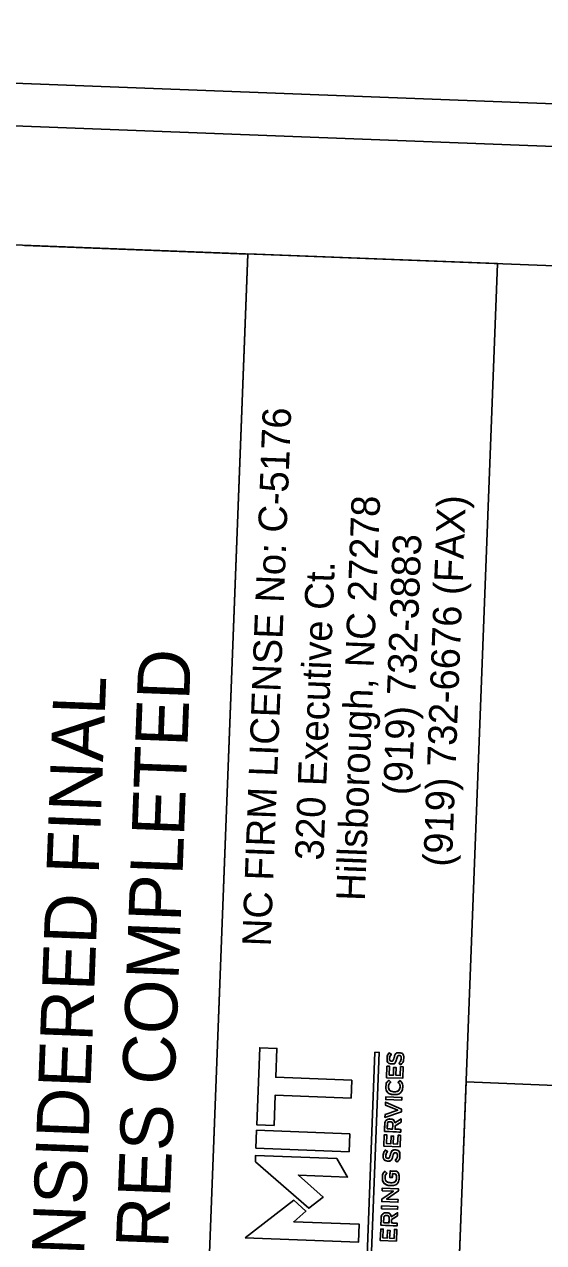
# Model space of a CAD drawing. Extents: x 2097096 to 2098260, y 686401 to 688363.
# Drawn here: x 2097322.3 to 2097376.9, y 688066.3 to 688194.3 of the extents above; entities that cross this region are included whole.
import ezdxf

# ---------------------------------------------------------------- set-up
doc = ezdxf.new("R2010")
doc.units = 0
for name, color, linetype in [('Sheet Block Title CELL', 7, 'Continuous'), ('Sheet Layout Plan Border', 7, 'Continuous'), ('Sheet Plot Border Inside CELL', 7, 'Continuous'), ('Sheet Plot Border Outside CELL', 7, 'Continuous'), ('Sheet Profile CELL', 7, 'Continuous'), ('Sheet Sticker Exception Certification CELL', 7, 'Continuous')]:
    doc.layers.add(name, color=color, linetype=linetype)

msp = doc.modelspace()

# ---------------------------------------------------------------- linework, layer by layer
at = {"layer": 'Sheet Block Title CELL'}
for p, q in [((2097360.85, 688086.12), (2097360.63, 688086.28)), ((2097361.66, 688086.29), (2097361.66, 688086.29)), ((2097360.86, 688085.41), (2097360.85, 688085.41)), ((2097360.87, 688085.12), (2097360.87, 688085.12)), ((2097361.64, 688085.2), (2097361.85, 688085.02)), ((2097361.67, 688086), (2097361.68, 688086)), ((2097360.78, 688083.2), (2097360.57, 688083.4)), ((2097361.76, 688083.36), (2097361.56, 688083.19)), ((2097361.14, 688082.19), (2097361.13, 688082.2)), ((2097361.13, 688081.89), (2097361.13, 688081.89)), ((2097360.72, 688079.33), (2097360.71, 688079.33)), ((2097360.72, 688079.04), (2097360.72, 688079.04)), ((2097360.46, 688075.91), (2097360.24, 688076.07)), ((2097361.27, 688076.08), (2097361.26, 688076.08)), ((2097360.47, 688075.2), (2097360.46, 688075.2)), ((2097360.48, 688074.91), (2097360.48, 688074.91)), ((2097361.25, 688074.99), (2097361.46, 688074.81)), ((2097361.28, 688075.79), (2097361.29, 688075.79)), ((2097360.39, 688073.64), (2097360.17, 688073.84)), ((2097360.76, 688072.34), (2097360.76, 688072.34)), ((2097360.77, 688072.64), (2097360.77, 688072.64)), ((2097360.34, 688069.48), (2097360.34, 688069.48)), ((2097360.34, 688069.19), (2097360.35, 688069.19))]:
    msp.add_line(p, q, dxfattribs=at)
msp.add_lwpolyline([(2097338.1, 687970.31), (2097345.76, 688170.22), (2097372, 688169.21), (2097364.33, 687969.3)], close=True, dxfattribs=at)
for points in [[(2097347.02, 688086.81), (2097348.83, 688086.74), (2097348.71, 688083.71), (2097356.69, 688083.4), (2097356.62, 688081.53), (2097348.64, 688081.83), (2097348.52, 688078.65), (2097346.71, 688078.72), (2097347.02, 688086.81)], [(2097346.71, 688078.72), (2097348.52, 688078.65), (2097348.64, 688081.83), (2097356.62, 688081.53), (2097356.69, 688083.4), (2097348.71, 688083.71), (2097348.83, 688086.74), (2097347.02, 688086.81), (2097346.71, 688078.72)], [(2097359.58, 688086.33), (2097357.83, 688040.83), (2097357.38, 688040.84), (2097359.13, 688086.35), (2097359.58, 688086.33)], [(2097359.13, 688086.35), (2097357.38, 688040.84), (2097357.83, 688040.83), (2097359.58, 688086.33), (2097359.13, 688086.35)], [(2097360.34, 688083.67), (2097360.39, 688084.88), (2097360.66, 688084.87), (2097360.62, 688083.95), (2097361.06, 688083.93), (2097361.09, 688084.75), (2097361.36, 688084.74), (2097361.33, 688083.92), (2097361.79, 688083.9), (2097361.82, 688084.84), (2097362.09, 688084.82), (2097362.04, 688083.61), (2097360.34, 688083.67)], [(2097362.04, 688083.61), (2097362.09, 688084.82), (2097361.82, 688084.84), (2097361.79, 688083.9), (2097361.33, 688083.92), (2097361.36, 688084.74), (2097361.09, 688084.75), (2097361.06, 688083.93), (2097360.62, 688083.95), (2097360.66, 688084.87), (2097360.39, 688084.88), (2097360.34, 688083.67), (2097362.04, 688083.61)], [(2097360.26, 688081.37), (2097360.27, 688081.66), (2097361.96, 688081.59), (2097361.95, 688081.31), (2097360.26, 688081.37)], [(2097361.95, 688081.31), (2097361.96, 688081.59), (2097360.27, 688081.66), (2097360.26, 688081.37), (2097361.95, 688081.31)], [(2097360.18, 688079.49), (2097360.2, 688079.81), (2097361.52, 688080.25), (2097360.23, 688080.79), (2097360.24, 688081.1), (2097361.93, 688080.36), (2097361.92, 688080.1), (2097360.18, 688079.49)], [(2097361.92, 688080.1), (2097361.93, 688080.36), (2097360.24, 688081.1), (2097360.23, 688080.79), (2097361.52, 688080.25), (2097360.2, 688079.81), (2097360.18, 688079.49), (2097361.92, 688080.1)], [(2097360.15, 688078.75), (2097360.13, 688078.02), (2097361.83, 688077.95), (2097361.84, 688078.24), (2097361.24, 688078.26), (2097361.26, 688078.62), (2097361.87, 688079), (2097361.88, 688079.34), (2097361.22, 688078.92)], [(2097361, 688078.69), (2097360.98, 688078.27), (2097360.41, 688078.3), (2097360.43, 688078.71)], [(2097346.62, 688076.27), (2097346.69, 688078.15), (2097356.48, 688077.77), (2097356.41, 688075.89), (2097346.62, 688076.27)], [(2097356.41, 688075.89), (2097356.48, 688077.77), (2097346.69, 688078.15), (2097346.62, 688076.27), (2097356.41, 688075.89)], [(2097360.07, 688076.46), (2097360.11, 688077.67), (2097360.38, 688077.66), (2097360.34, 688076.74), (2097360.79, 688076.72), (2097360.82, 688077.54), (2097361.08, 688077.53), (2097361.05, 688076.71), (2097361.51, 688076.69), (2097361.55, 688077.63), (2097361.81, 688077.62), (2097361.77, 688076.4), (2097360.07, 688076.46)], [(2097361.77, 688076.4), (2097361.81, 688077.62), (2097361.55, 688077.63), (2097361.51, 688076.69), (2097361.05, 688076.71), (2097361.08, 688077.53), (2097360.82, 688077.54), (2097360.79, 688076.72), (2097360.34, 688076.74), (2097360.38, 688077.66), (2097360.11, 688077.67), (2097360.07, 688076.46), (2097361.77, 688076.4)], [(2097346.56, 688074.84), (2097352.18, 688069.95), (2097353.69, 688071.13), (2097351.08, 688073.43), (2097356.25, 688073.23), (2097355.12, 688075.17), (2097346.59, 688075.5), (2097346.56, 688074.84)], [(2097346.56, 688074.84), (2097352.18, 688069.95), (2097353.69, 688071.13), (2097351.08, 688073.43), (2097356.25, 688073.23), (2097355.12, 688075.17), (2097346.59, 688075.5), (2097346.56, 688074.84)], [(2097361.43, 688073.85), (2097360.72, 688073.87), (2097360.69, 688073.18), (2097360.95, 688073.17), (2097360.97, 688073.59), (2097361.29, 688073.57)], [(2097359.84, 688070.66), (2097359.85, 688070.92), (2097361.06, 688071.75), (2097359.89, 688071.79), (2097359.9, 688072.08), (2097361.6, 688072.01), (2097361.59, 688071.77), (2097360.35, 688070.92), (2097361.55, 688070.87), (2097361.54, 688070.59), (2097359.84, 688070.66)], [(2097361.54, 688070.59), (2097361.55, 688070.87), (2097360.35, 688070.92), (2097361.59, 688071.77), (2097361.6, 688072.01), (2097359.9, 688072.08), (2097359.89, 688071.79), (2097361.06, 688071.75), (2097359.85, 688070.92), (2097359.84, 688070.66), (2097361.54, 688070.59)], [(2097345.48, 688066.86), (2097357.4, 688066.4), (2097357.47, 688068.28), (2097350.59, 688068.54), (2097351.87, 688069.66), (2097350.61, 688070.8), (2097345.48, 688066.86)], [(2097345.48, 688066.86), (2097357.4, 688066.4), (2097357.47, 688068.28), (2097350.59, 688068.54), (2097351.87, 688069.66), (2097350.61, 688070.8), (2097345.48, 688066.86)], [(2097359.82, 688069.91), (2097359.83, 688070.2), (2097361.53, 688070.13), (2097361.51, 688069.85), (2097359.82, 688069.91)], [(2097361.51, 688069.85), (2097361.53, 688070.13), (2097359.83, 688070.2), (2097359.82, 688069.91), (2097361.51, 688069.85)], [(2097359.78, 688068.89), (2097359.75, 688068.17), (2097361.45, 688068.1), (2097361.46, 688068.39), (2097360.87, 688068.41), (2097360.88, 688068.77), (2097361.49, 688069.15), (2097361.5, 688069.49), (2097360.84, 688069.07)], [(2097360.62, 688068.84), (2097360.6, 688068.42), (2097360.03, 688068.44), (2097360.05, 688068.86)], [(2097359.69, 688066.56), (2097359.73, 688067.77), (2097360, 688067.76), (2097359.97, 688066.84), (2097360.41, 688066.82), (2097360.44, 688067.64), (2097360.71, 688067.63), (2097360.67, 688066.81), (2097361.13, 688066.79), (2097361.17, 688067.73), (2097361.43, 688067.72), (2097361.39, 688066.5), (2097359.69, 688066.56)], [(2097361.39, 688066.5), (2097361.43, 688067.72), (2097361.17, 688067.73), (2097361.13, 688066.79), (2097360.67, 688066.81), (2097360.71, 688067.63), (2097360.44, 688067.64), (2097360.41, 688066.82), (2097359.97, 688066.84), (2097360, 688067.76), (2097359.73, 688067.77), (2097359.69, 688066.56), (2097361.39, 688066.5)]]:
    msp.add_lwpolyline(points, dxfattribs=at)
for points, degree in [([(2097361.85, 688085.02), (2097361.85, 688085.02), (2097361.64, 688085.2), (2097361.64, 688085.2), (2097361.79, 688085.35), (2097361.87, 688085.5), (2097361.88, 688085.7), (2097361.89, 688085.88), (2097361.81, 688086), (2097361.68, 688086), (2097361.68, 688086), (2097361.67, 688086), (2097361.67, 688086), (2097361.55, 688086.01), (2097361.49, 688085.94), (2097361.4, 688085.64), (2097361.3, 688085.3), (2097361.19, 688085.11), (2097360.87, 688085.12), (2097360.87, 688085.12), (2097360.87, 688085.12), (2097360.87, 688085.12), (2097360.58, 688085.13), (2097360.38, 688085.37), (2097360.4, 688085.7), (2097360.41, 688085.93), (2097360.49, 688086.12), (2097360.63, 688086.28), (2097360.63, 688086.28), (2097360.85, 688086.12), (2097360.85, 688086.12), (2097360.73, 688085.97), (2097360.67, 688085.83), (2097360.66, 688085.68), (2097360.65, 688085.51), (2097360.74, 688085.41), (2097360.85, 688085.41), (2097360.85, 688085.41), (2097360.86, 688085.41), (2097360.86, 688085.41), (2097360.99, 688085.4), (2097361.05, 688085.48), (2097361.14, 688085.79), (2097361.24, 688086.13), (2097361.37, 688086.3), (2097361.66, 688086.29), (2097361.66, 688086.29), (2097361.66, 688086.29), (2097361.66, 688086.29), (2097361.98, 688086.28), (2097362.16, 688086.03), (2097362.15, 688085.69), (2097362.14, 688085.44), (2097362.04, 688085.21), (2097361.85, 688085.02)], 3), ([(2097360.63, 688086.28), (2097360.49, 688086.12), (2097360.41, 688085.93), (2097360.4, 688085.7), (2097360.38, 688085.37), (2097360.58, 688085.13), (2097360.87, 688085.12)], 3), ([(2097361.66, 688086.29), (2097361.37, 688086.3), (2097361.24, 688086.13), (2097361.14, 688085.79), (2097361.05, 688085.48), (2097360.99, 688085.4), (2097360.86, 688085.41)], 3), ([(2097361.85, 688085.02), (2097362.04, 688085.21), (2097362.14, 688085.44), (2097362.15, 688085.69), (2097362.16, 688086.03), (2097361.98, 688086.28), (2097361.66, 688086.29)], 3), ([(2097360.85, 688085.41), (2097360.74, 688085.41), (2097360.65, 688085.51), (2097360.66, 688085.68), (2097360.67, 688085.83), (2097360.73, 688085.97), (2097360.85, 688086.12)], 3), ([(2097360.87, 688085.12), (2097361.19, 688085.11), (2097361.3, 688085.3), (2097361.4, 688085.64), (2097361.49, 688085.94), (2097361.55, 688086.01), (2097361.67, 688086)], 3), ([(2097361.68, 688086), (2097361.81, 688086), (2097361.89, 688085.88), (2097361.88, 688085.7), (2097361.87, 688085.5), (2097361.79, 688085.35), (2097361.64, 688085.2)], 3), ([(2097361.13, 688081.89), (2097361.13, 688081.89), (2097361.13, 688081.89), (2097361.13, 688081.89), (2097360.64, 688081.91), (2097360.26, 688082.28), (2097360.28, 688082.77), (2097360.29, 688083.07), (2097360.41, 688083.25), (2097360.57, 688083.4), (2097360.57, 688083.4), (2097360.78, 688083.2), (2097360.78, 688083.2), (2097360.65, 688083.08), (2097360.56, 688082.94), (2097360.55, 688082.76), (2097360.54, 688082.45), (2097360.8, 688082.21), (2097361.13, 688082.2), (2097361.13, 688082.2), (2097361.14, 688082.19), (2097361.14, 688082.19), (2097361.47, 688082.18), (2097361.75, 688082.4), (2097361.76, 688082.71), (2097361.77, 688082.91), (2097361.69, 688083.04), (2097361.56, 688083.19), (2097361.56, 688083.19), (2097361.76, 688083.36), (2097361.76, 688083.36), (2097361.94, 688083.19), (2097362.05, 688082.99), (2097362.04, 688082.69), (2097362.02, 688082.21), (2097361.62, 688081.88), (2097361.13, 688081.89)], 3), ([(2097360.57, 688083.4), (2097360.41, 688083.25), (2097360.29, 688083.07), (2097360.28, 688082.77), (2097360.26, 688082.28), (2097360.64, 688081.91), (2097361.13, 688081.89)], 3), ([(2097361.13, 688082.2), (2097360.8, 688082.21), (2097360.54, 688082.45), (2097360.55, 688082.76), (2097360.56, 688082.94), (2097360.65, 688083.08), (2097360.78, 688083.2)], 3), ([(2097361.13, 688081.89), (2097361.62, 688081.88), (2097362.02, 688082.21), (2097362.04, 688082.69), (2097362.05, 688082.99), (2097361.94, 688083.19), (2097361.76, 688083.36)], 3), ([(2097361.56, 688083.19), (2097361.69, 688083.04), (2097361.77, 688082.91), (2097361.76, 688082.71), (2097361.75, 688082.4), (2097361.47, 688082.18), (2097361.14, 688082.19)], 3), ([(2097360.13, 688078.02), (2097360.13, 688078.02), (2097360.15, 688078.75), (2097360.15, 688078.75), (2097360.16, 688078.95), (2097360.23, 688079.11), (2097360.34, 688079.21), (2097360.44, 688079.29), (2097360.57, 688079.34), (2097360.71, 688079.33), (2097360.71, 688079.33), (2097360.72, 688079.33), (2097360.72, 688079.33), (2097361, 688079.32), (2097361.16, 688079.15), (2097361.22, 688078.92), (2097361.22, 688078.92), (2097361.88, 688079.34), (2097361.88, 688079.34), (2097361.88, 688079.34), (2097361.87, 688079), (2097361.87, 688079), (2097361.87, 688079), (2097361.26, 688078.62), (2097361.26, 688078.62), (2097361.26, 688078.62), (2097361.24, 688078.26), (2097361.24, 688078.26), (2097361.24, 688078.26), (2097361.84, 688078.24), (2097361.84, 688078.24), (2097361.84, 688078.24), (2097361.83, 688077.95), (2097361.83, 688077.95), (2097361.83, 688077.95), (2097360.13, 688078.02), (2097360.13, 688078.02)], 3), ([(2097360.71, 688079.33), (2097360.57, 688079.34), (2097360.44, 688079.29), (2097360.34, 688079.21), (2097360.23, 688079.11), (2097360.16, 688078.95), (2097360.15, 688078.75)], 3), ([(2097361, 688078.69), (2097361, 688078.9), (2097360.9, 688079.03), (2097360.72, 688079.04), (2097360.72, 688079.04), (2097360.72, 688079.04), (2097360.72, 688079.04), (2097360.54, 688079.05), (2097360.43, 688078.92), (2097360.43, 688078.71), (2097360.43, 688078.71), (2097360.41, 688078.3), (2097360.41, 688078.3), (2097360.41, 688078.3), (2097360.98, 688078.27), (2097360.98, 688078.27), (2097360.98, 688078.27), (2097361, 688078.69), (2097361, 688078.69)], 3), ([(2097360.43, 688078.71), (2097360.43, 688078.92), (2097360.54, 688079.05), (2097360.72, 688079.04)], 2), ([(2097361.22, 688078.92), (2097361.16, 688079.15), (2097361, 688079.32), (2097360.72, 688079.33)], 2), ([(2097360.72, 688079.04), (2097360.9, 688079.03), (2097361, 688078.9), (2097361, 688078.69)], 2), ([(2097361.46, 688074.81), (2097361.46, 688074.81), (2097361.25, 688074.99), (2097361.25, 688074.99), (2097361.4, 688075.14), (2097361.48, 688075.29), (2097361.49, 688075.49), (2097361.5, 688075.67), (2097361.41, 688075.78), (2097361.29, 688075.79), (2097361.29, 688075.79), (2097361.28, 688075.79), (2097361.28, 688075.79), (2097361.16, 688075.79), (2097361.09, 688075.73), (2097361.01, 688075.43), (2097360.91, 688075.09), (2097360.79, 688074.9), (2097360.48, 688074.91), (2097360.48, 688074.91), (2097360.48, 688074.91), (2097360.48, 688074.91), (2097360.19, 688074.92), (2097359.99, 688075.16), (2097360, 688075.48), (2097360.01, 688075.72), (2097360.1, 688075.91), (2097360.24, 688076.07), (2097360.24, 688076.07), (2097360.46, 688075.91), (2097360.46, 688075.91), (2097360.34, 688075.76), (2097360.28, 688075.62), (2097360.27, 688075.47), (2097360.26, 688075.3), (2097360.35, 688075.2), (2097360.46, 688075.2), (2097360.46, 688075.2), (2097360.47, 688075.2), (2097360.47, 688075.2), (2097360.6, 688075.19), (2097360.66, 688075.26), (2097360.75, 688075.57), (2097360.85, 688075.92), (2097360.98, 688076.09), (2097361.26, 688076.08), (2097361.26, 688076.08), (2097361.27, 688076.08), (2097361.27, 688076.08), (2097361.59, 688076.06), (2097361.77, 688075.82), (2097361.75, 688075.48), (2097361.75, 688075.23), (2097361.65, 688074.99), (2097361.46, 688074.81)], 3), ([(2097360.24, 688076.07), (2097360.1, 688075.91), (2097360.01, 688075.72), (2097360, 688075.48), (2097359.99, 688075.16), (2097360.19, 688074.92), (2097360.48, 688074.91)], 3), ([(2097361.26, 688076.08), (2097360.98, 688076.09), (2097360.85, 688075.92), (2097360.75, 688075.57), (2097360.66, 688075.26), (2097360.6, 688075.19), (2097360.47, 688075.2)], 3), ([(2097361.46, 688074.81), (2097361.65, 688074.99), (2097361.75, 688075.23), (2097361.75, 688075.48), (2097361.77, 688075.82), (2097361.59, 688076.06), (2097361.27, 688076.08)], 3), ([(2097360.46, 688075.2), (2097360.35, 688075.2), (2097360.26, 688075.3), (2097360.27, 688075.47), (2097360.28, 688075.62), (2097360.34, 688075.76), (2097360.46, 688075.91)], 3), ([(2097360.48, 688074.91), (2097360.79, 688074.9), (2097360.91, 688075.09), (2097361.01, 688075.43), (2097361.09, 688075.73), (2097361.16, 688075.79), (2097361.28, 688075.79)], 3), ([(2097361.29, 688075.79), (2097361.41, 688075.78), (2097361.5, 688075.67), (2097361.49, 688075.49), (2097361.48, 688075.29), (2097361.4, 688075.14), (2097361.25, 688074.99)], 3), ([(2097360.76, 688072.34), (2097360.76, 688072.34), (2097360.76, 688072.34), (2097360.76, 688072.34), (2097360.28, 688072.36), (2097359.89, 688072.73), (2097359.91, 688073.22), (2097359.92, 688073.5), (2097360.01, 688073.67), (2097360.17, 688073.84), (2097360.17, 688073.84), (2097360.39, 688073.64), (2097360.39, 688073.64), (2097360.27, 688073.52), (2097360.19, 688073.4), (2097360.19, 688073.2), (2097360.18, 688072.9), (2097360.44, 688072.66), (2097360.77, 688072.64), (2097360.77, 688072.64), (2097360.77, 688072.64), (2097360.77, 688072.64), (2097361.12, 688072.63), (2097361.39, 688072.84), (2097361.4, 688073.17), (2097361.4, 688073.33), (2097361.36, 688073.47), (2097361.29, 688073.57), (2097361.29, 688073.57), (2097360.97, 688073.59), (2097360.97, 688073.59), (2097360.97, 688073.59), (2097360.95, 688073.17), (2097360.95, 688073.17), (2097360.95, 688073.17), (2097360.69, 688073.18), (2097360.69, 688073.18), (2097360.69, 688073.18), (2097360.72, 688073.87), (2097360.72, 688073.87), (2097360.72, 688073.87), (2097361.43, 688073.85), (2097361.43, 688073.85), (2097361.57, 688073.68), (2097361.68, 688073.44), (2097361.67, 688073.15), (2097361.65, 688072.65), (2097361.26, 688072.32), (2097360.76, 688072.34)], 3), ([(2097360.17, 688073.84), (2097360.01, 688073.67), (2097359.92, 688073.5), (2097359.91, 688073.22), (2097359.89, 688072.73), (2097360.28, 688072.36), (2097360.76, 688072.34)], 3), ([(2097360.77, 688072.64), (2097360.44, 688072.66), (2097360.18, 688072.9), (2097360.19, 688073.2), (2097360.19, 688073.4), (2097360.27, 688073.52), (2097360.39, 688073.64)], 3), ([(2097360.76, 688072.34), (2097361.26, 688072.32), (2097361.65, 688072.65), (2097361.67, 688073.15), (2097361.68, 688073.44), (2097361.57, 688073.68), (2097361.43, 688073.85)], 3), ([(2097361.29, 688073.57), (2097361.36, 688073.47), (2097361.4, 688073.33), (2097361.4, 688073.17), (2097361.39, 688072.84), (2097361.12, 688072.63), (2097360.77, 688072.64)], 3), ([(2097359.75, 688068.17), (2097359.75, 688068.17), (2097359.78, 688068.89), (2097359.78, 688068.89), (2097359.78, 688069.1), (2097359.85, 688069.26), (2097359.96, 688069.36), (2097360.06, 688069.44), (2097360.19, 688069.48), (2097360.34, 688069.48), (2097360.34, 688069.48), (2097360.34, 688069.48), (2097360.34, 688069.48), (2097360.62, 688069.47), (2097360.78, 688069.3), (2097360.84, 688069.07), (2097360.84, 688069.07), (2097361.5, 688069.49), (2097361.5, 688069.49), (2097361.5, 688069.49), (2097361.49, 688069.15), (2097361.49, 688069.15), (2097361.49, 688069.15), (2097360.88, 688068.77), (2097360.88, 688068.77), (2097360.88, 688068.77), (2097360.87, 688068.41), (2097360.87, 688068.41), (2097360.87, 688068.41), (2097361.46, 688068.39), (2097361.46, 688068.39), (2097361.46, 688068.39), (2097361.45, 688068.1), (2097361.45, 688068.1), (2097361.45, 688068.1), (2097359.75, 688068.17), (2097359.75, 688068.17)], 3), ([(2097360.34, 688069.48), (2097360.19, 688069.48), (2097360.06, 688069.44), (2097359.96, 688069.36), (2097359.85, 688069.26), (2097359.78, 688069.1), (2097359.78, 688068.89)], 3), ([(2097360.62, 688068.84), (2097360.63, 688069.04), (2097360.52, 688069.18), (2097360.35, 688069.19), (2097360.35, 688069.19), (2097360.34, 688069.19), (2097360.34, 688069.19), (2097360.16, 688069.19), (2097360.06, 688069.07), (2097360.05, 688068.86), (2097360.05, 688068.86), (2097360.03, 688068.44), (2097360.03, 688068.44), (2097360.03, 688068.44), (2097360.6, 688068.42), (2097360.6, 688068.42), (2097360.6, 688068.42), (2097360.62, 688068.84), (2097360.62, 688068.84)], 3), ([(2097360.05, 688068.86), (2097360.06, 688069.07), (2097360.16, 688069.19), (2097360.34, 688069.19)], 2), ([(2097360.84, 688069.07), (2097360.78, 688069.3), (2097360.62, 688069.47), (2097360.34, 688069.48)], 2), ([(2097360.35, 688069.19), (2097360.52, 688069.18), (2097360.63, 688069.04), (2097360.62, 688068.84)], 2)]:
    msp.add_open_spline(points, degree=degree, dxfattribs=at)
at = {"layer": 'Sheet Layout Plan Border'}
msp.add_lwpolyline([(2098179.19, 686705.44), (2097129.59, 686735.95), (2097177.17, 687976.48), (2097364.33, 687969.3), (2097368.7, 688083.22), (2098230.76, 688050.16)], close=True, dxfattribs=at)
at = {"layer": 'Sheet Plot Border Inside CELL'}
msp.add_lwpolyline([(2098173.22, 686483.26), (2098237.09, 688148.54), (2097182.76, 688188.97), (2097118.9, 686523.7)], close=True, dxfattribs=at)
at = {"layer": 'Sheet Plot Border Outside CELL'}
msp.add_lwpolyline([(2098195.16, 686469.41), (2098259.69, 688152.17), (2097160.5, 688194.33), (2097095.97, 686511.57)], close=True, dxfattribs=at)
at = {"layer": 'Sheet Profile CELL'}
msp.add_lwpolyline([(2097184.83, 688176.38), (2097127.35, 686677.48), (2098176.58, 686637.25), (2098234.06, 688136.14)], close=True, dxfattribs=at)
at = {"layer": 'Sheet Sticker Exception Certification CELL'}
for p, q in [((2097322.29, 688171.1), (2097345.78, 688170.2)), ((2097345.76, 688170.2), (2097338.1, 687970.31))]:
    msp.add_line(p, q, dxfattribs=at)

# ---------------------------------------------------------------- texts
at = {"layer": 'Sheet Block Title CELL'}
for s, p in [('NC FIRM LICENSE No: C-5176', (2097348.17, 688097.43)), ('Hillsborough, NC 27278', (2097358.05, 688102.2)), ('(919) 732-6676 (FAX)', (2097367.2, 688105.8)), ('(919) 732-3883', (2097362.98, 688113.31)), ('320 Executive Ct.', (2097353.71, 688106.46))]:
    msp.add_text(s, height=3.0009, rotation=87.8037, dxfattribs=at).set_placement(p)
at = {"layer": 'Sheet Sticker Exception Certification CELL'}
for s, p in [('UNLESS ALL SIGNATURES COMPLETED', (2097334.36, 687986.46)), ('DOCUMENT NOT CONSIDERED FINAL', (2097325.76, 687991.87))]:
    msp.add_text(s, height=5.5, rotation=87.8037, dxfattribs=at).set_placement(p)

doc.saveas('drawing.dxf')
